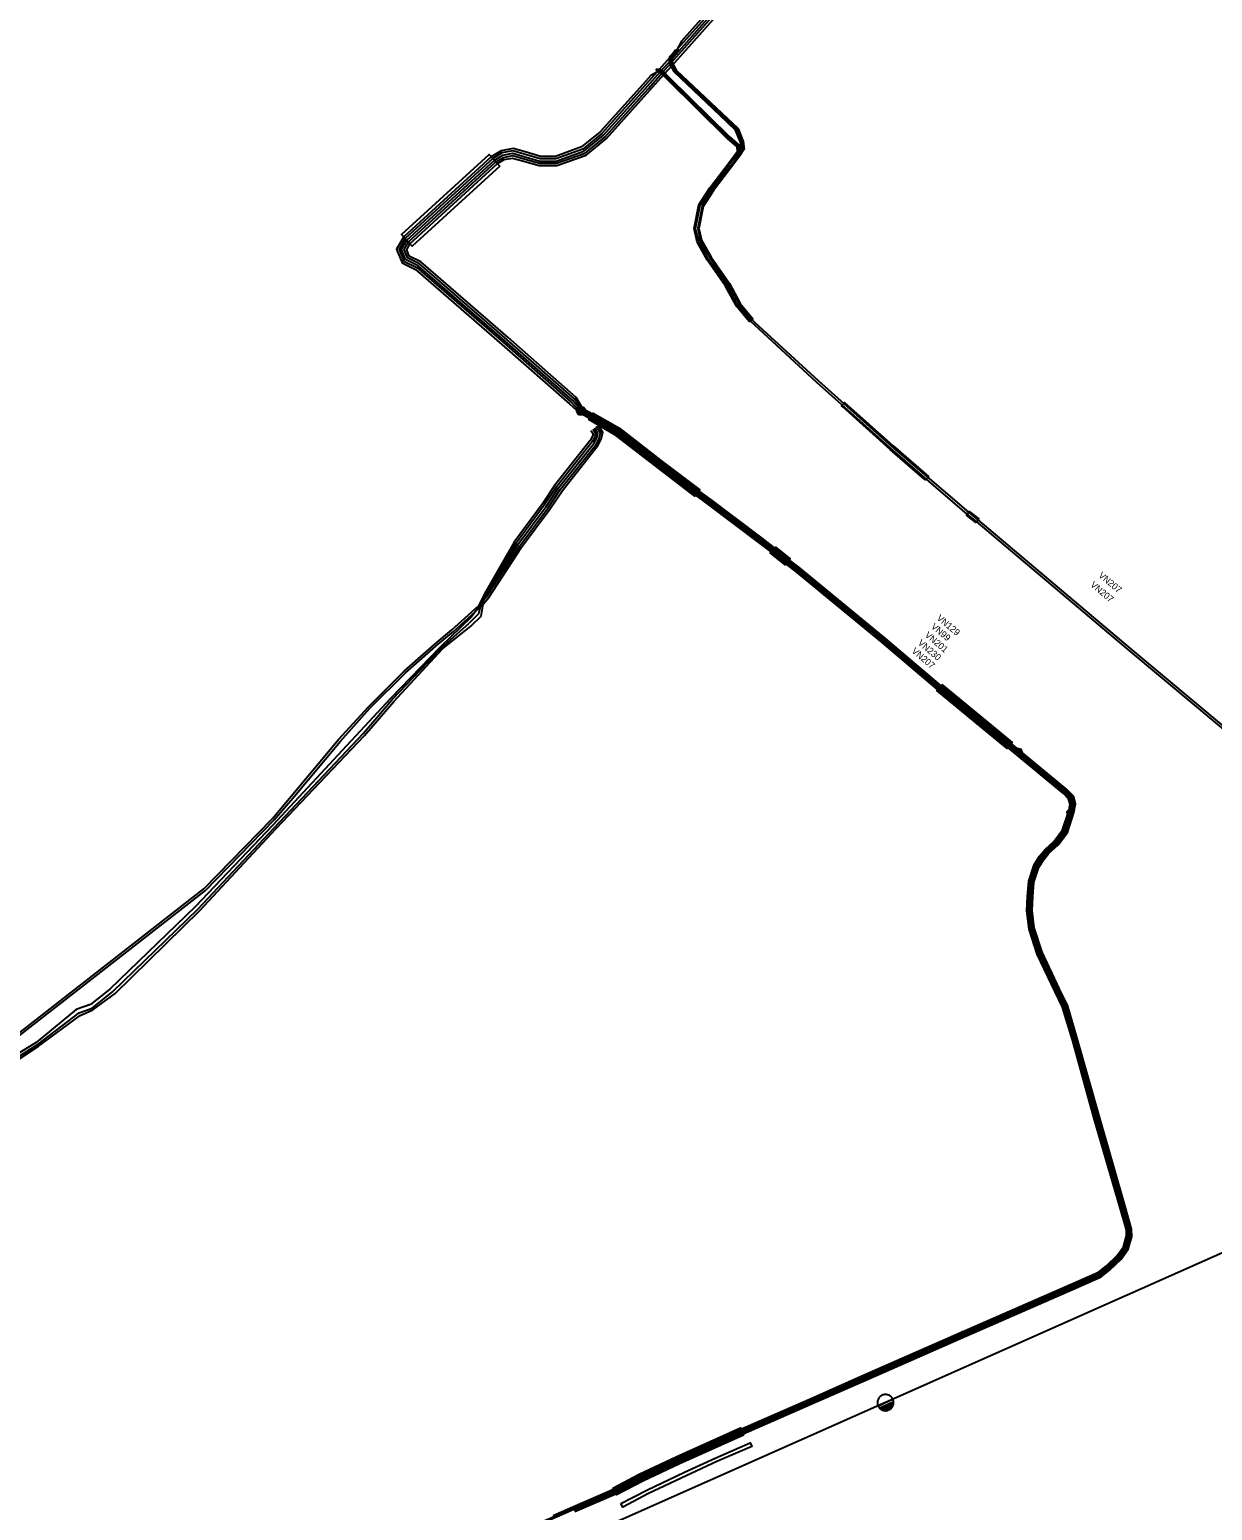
# Model space of a CAD drawing. Extents: x -643811 to -636362, y -1117362 to -1108614.
# Drawn here: x -640773 to -640592.9, y -1115901 to -1115675.5 of the extents above; entities that cross this region are included whole.
import ezdxf

# ---------------------------------------------------------------- set-up
doc = ezdxf.new("R2010")
doc.units = 0
for name, color, linetype in [('1', 7, 'Continuous'), ('13', 7, 'Continuous'), ('19', 7, 'Continuous'), ('20', 7, 'Continuous'), ('5', 7, 'Continuous'), ('7', 7, 'Continuous'), ('9', 7, 'Continuous')]:
    doc.layers.add(name, color=color, linetype=linetype)

# ---------------------------------------------------------------- blocks, each defined once
blk = doc.blocks.new('VN440')
at = {"layer": '13'}
for points in [[(1.22, 0), (1.21, 0.13), (1.19, 0.25), (1.16, 0.38), (1.11, 0.5), (1.05, 0.61), (0.98, 0.72), (0.9, 0.82), (0.81, 0.91), (0.71, 0.99), (0.6, 1.06), (0.49, 1.12), (0.37, 1.16), (0.25, 1.2), (0.12, 1.22), (-0.01, 1.22), (-0.14, 1.22), (-0.26, 1.2), (-0.39, 1.16), (-0.51, 1.12), (-0.62, 1.06), (-0.73, 0.99), (-0.83, 0.91), (-0.92, 0.82), (-1, 0.72), (-1.07, 0.61), (-1.13, 0.5), (-1.18, 0.38), (-1.21, 0.25), (-1.23, 0.13), (-1.24, 0), (-1.23, -0.13), (-1.21, -0.26), (-1.18, -0.38), (-1.13, -0.5), (-1.07, -0.62), (-1, -0.73), (-0.92, -0.83), (-0.83, -0.92), (-0.73, -1), (-0.62, -1.07), (-0.51, -1.13), (-0.39, -1.17), (-0.26, -1.2), (-0.14, -1.23), (-0.01, -1.23), (0.12, -1.23), (0.25, -1.2), (0.37, -1.17), (0.49, -1.13), (0.6, -1.07), (0.71, -1), (0.81, -0.92), (0.9, -0.83), (0.98, -0.73), (1.05, -0.62), (1.11, -0.5), (1.16, -0.38), (1.19, -0.26), (1.21, -0.13), (1.22, 0)], [(-1.24, 0), (1.22, 0)], [(-1.18, -0.34), (1.1, -0.34)], [(-1.01, -0.63), (0.97, -0.63)], [(-0.74, -0.92), (0.68, -0.92)]]:
    blk.add_lwpolyline(points, dxfattribs=at)
blk = doc.blocks.new('VN870')
at = {"layer": '19'}
for points in [[(0, -0.25), (0.5, 0), (0, 0.25), (-0.5, 0), (0, -0.25)], [(0.37, 0), (0, 0.19), (-0.36, 0), (0, -0.19), (0.37, 0)], [(0.24, 0), (0, 0.12), (-0.25, 0), (0, -0.12), (0.24, 0)], [(0.12, 0), (0, 0.06), (-0.13, 0), (0, -0.06), (0.12, 0)]]:
    blk.add_lwpolyline(points, dxfattribs=at)

msp = doc.modelspace()

# ---------------------------------------------------------------- linework, layer by layer
at = {"layer": '1'}
msp.add_lwpolyline([(-640174.13, -1115803.89), (-640251.81, -1115797.69), (-640320.19, -1115797.01), (-640382.28, -1115796.07), (-640441.87, -1115795.49), (-640509.03, -1115825.24), (-640529.18, -1115834.18), (-640529.51, -1115834.33), (-640569.54, -1115852.09), (-640642.67, -1115884.59), (-640695.7, -1115908.15), (-640695.88, -1115908.23), (-640712.05, -1115915.41), (-640778.4, -1115945.12), (-640781.72, -1115942.1), (-640781.89, -1115941.95), (-640782.05, -1115941.8), (-640782.21, -1115941.65), (-640782.37, -1115941.51), (-640806.72, -1115919.38), (-640845, -1115909.84)], dxfattribs=at)
at = {"layer": '20'}
for points in [[(-640674.7, -1115681.77), (-640674.87, -1115681.87), (-640675.56, -1115680.63), (-640675.5, -1115679.58), (-640674.75, -1115678.76), (-640674.45, -1115679.03), (-640675.1, -1115679.74), (-640675.16, -1115680.53), (-640674.54, -1115681.65), (-640674.53, -1115681.67)], [(-640675.72, -1115682.97), (-640675.86, -1115683.11), (-640676.77, -1115682.16), (-640677.21, -1115681.95), (-640677.03, -1115681.59), (-640676.53, -1115681.84), (-640675.58, -1115682.83), (-640675.58, -1115682.83)], [(-640675.58, -1115682.83), (-640675.58, -1115682.83), (-640666.48, -1115691.79), (-640666.48, -1115691.79), (-640666.62, -1115691.93), (-640666.76, -1115692.07), (-640675.86, -1115683.11), (-640675.72, -1115682.97)], [(-640674.7, -1115681.77), (-640674.56, -1115681.62), (-640674.54, -1115681.65), (-640667.55, -1115688.28), (-640665.18, -1115690.53), (-640665.32, -1115690.68), (-640665.46, -1115690.82), (-640665.49, -1115690.8), (-640667.83, -1115688.57), (-640674.84, -1115681.91)], [(-640666.62, -1115691.93), (-640666.49, -1115691.78), (-640666.48, -1115691.79), (-640664.87, -1115693.18), (-640664.83, -1115693.91), (-640664.82, -1115694.04), (-640664.92, -1115694.04), (-640665.02, -1115694.05), (-640665.22, -1115694.06), (-640665.22, -1115693.99), (-640665.26, -1115693.37), (-640666.75, -1115692.08)], [(-640665.32, -1115690.68), (-640665.13, -1115690.61), (-640664.35, -1115692.52), (-640664.19, -1115693.68), (-640664.61, -1115694.3), (-640664.94, -1115694.07), (-640664.92, -1115694.04), (-640664.83, -1115693.91), (-640664.61, -1115693.58), (-640664.75, -1115692.62), (-640665.49, -1115690.8), (-640665.51, -1115690.76)], [(-640665.22, -1115693.99), (-640665.18, -1115693.93), (-640665.02, -1115694.05), (-640664.62, -1115694.34), (-640665.78, -1115695.95), (-640668.87, -1115700.01), (-640670.43, -1115702.44), (-640671.08, -1115705.78), (-640670.68, -1115707.56), (-640669.23, -1115710.17), (-640666.42, -1115714.18), (-640664.78, -1115717.23), (-640662.88, -1115719.52), (-640663.42, -1115719.97), (-640665.37, -1115717.62), (-640667.02, -1115714.55), (-640669.82, -1115710.55), (-640671.34, -1115707.81), (-640671.79, -1115705.79), (-640671.09, -1115702.17), (-640669.44, -1115699.6), (-640666.34, -1115695.53)], [(-640701.4, -1115696.27), (-640714.73, -1115708.47), (-640716.35, -1115706.7), (-640703.02, -1115694.5)], [(-640649.19, -1115732.97), (-640649.37, -1115732.81), (-640648.9, -1115732.29), (-640641.51, -1115738.89), (-640636.15, -1115743.53), (-640636.61, -1115744.06), (-640636.97, -1115743.75), (-640641.97, -1115739.42)], [(-640687.26, -1115733.85), (-640683.19, -1115736.21), (-640683.12, -1115736.25), (-640676.46, -1115741.4), (-640670.96, -1115745.58), (-640671.68, -1115746.54), (-640677.2, -1115742.36), (-640683.8, -1115737.25), (-640687.86, -1115734.89)], [(-640630.13, -1115749.16), (-640629.93, -1115748.91), (-640628.49, -1115750.02), (-640628.74, -1115750.34), (-640628.92, -1115750.58), (-640630.36, -1115749.46)], [(-640659.46, -1115754.26), (-640657.2, -1115756.08), (-640657.96, -1115757.02), (-640660.22, -1115755.2)], [(-640634.12, -1115775.23), (-640623.39, -1115784.07), (-640624.15, -1115784.99), (-640634.88, -1115776.15)], [(-640684.2, -1115897.6), (-640680.19, -1115895.51), (-640674.53, -1115892.84), (-640664.77, -1115888.44), (-640664.29, -1115889.54), (-640674.03, -1115893.94), (-640679.63, -1115896.58), (-640683.64, -1115898.66)], [(-640682.96, -1115899.97), (-640679.03, -1115897.93), (-640673.28, -1115895.19), (-640668.61, -1115893.03), (-640663.29, -1115890.72), (-640663.05, -1115891.27), (-640668.37, -1115893.57), (-640673.02, -1115895.73), (-640678.76, -1115898.46), (-640682.68, -1115900.51)]]:
    msp.add_lwpolyline(points, close=True, dxfattribs=at)
at = {"layer": '5'}
for points in [[(-640595.84, -1115583.46), (-640600.55, -1115588.86), (-640608.04, -1115597.9), (-640613.88, -1115605.07), (-640619.92, -1115612.2), (-640634.62, -1115629.42), (-640648.36, -1115645.76), (-640650.75, -1115648.6), (-640669.54, -1115672.54), (-640673.71, -1115677.27), (-640674.38, -1115678.49), (-640674.6, -1115678.9)], [(-640669.28, -1115672.77), (-640674.38, -1115678.49), (-640677.48, -1115681.97), (-640679.21, -1115683.92), (-640685.86, -1115691.33), (-640688.77, -1115693.68), (-640692.89, -1115695.16), (-640695.26, -1115695.16), (-640697.67, -1115694.46), (-640699.4, -1115693.97), (-640701.09, -1115694.28), (-640702.45, -1115695.13), (-640715.78, -1115707.33), (-640716.73, -1115708.95), (-640716.01, -1115710.75), (-640714.02, -1115711.75), (-640700.85, -1115723.16), (-640690.51, -1115732.24), (-640689.14, -1115733.72)], [(-640689.01, -1115733.56), (-640690.26, -1115731.99), (-640700.65, -1115722.88), (-640713.82, -1115711.46), (-640715.73, -1115710.5), (-640716.34, -1115708.97), (-640715.54, -1115707.58), (-640702.21, -1115695.38), (-640700.96, -1115694.61), (-640699.41, -1115694.33), (-640697.76, -1115694.8), (-640695.31, -1115695.51), (-640692.82, -1115695.51), (-640688.6, -1115693.99), (-640685.63, -1115691.59), (-640678.93, -1115684.13), (-640676.92, -1115681.87), (-640675.33, -1115680.08), (-640669.01, -1115673)], [(-640688.88, -1115733.4), (-640690, -1115731.75), (-640700.35, -1115722.67), (-640713.63, -1115711.16), (-640715.45, -1115710.24), (-640715.96, -1115709), (-640715.31, -1115707.84), (-640701.98, -1115695.64), (-640700.83, -1115694.95), (-640699.43, -1115694.69), (-640697.87, -1115695.13), (-640695.36, -1115695.86), (-640692.76, -1115695.86), (-640688.42, -1115694.3), (-640685.38, -1115691.84), (-640678.82, -1115684.52), (-640676.61, -1115682.04), (-640675.34, -1115680.62), (-640668.74, -1115673.22)], [(-640688.75, -1115733.25), (-640689.75, -1115731.51), (-640700.13, -1115722.4), (-640713.43, -1115710.87), (-640715.18, -1115709.99), (-640715.57, -1115709.02), (-640715.07, -1115708.1), (-640701.74, -1115695.9), (-640700.71, -1115695.28), (-640699.45, -1115695.05), (-640697.95, -1115695.47), (-640695.41, -1115696.21), (-640692.7, -1115696.21), (-640688.25, -1115694.61), (-640685.14, -1115692.1), (-640678.54, -1115684.74), (-640676.36, -1115682.3), (-640675.16, -1115680.94), (-640668.47, -1115673.44)], [(-640674.6, -1115678.9), (-640675.3, -1115679.66), (-640675.33, -1115680.08), (-640675.36, -1115680.58), (-640675.34, -1115680.62), (-640675.16, -1115680.94), (-640674.7, -1115681.77), (-640667.69, -1115688.42), (-640665.32, -1115690.68), (-640664.55, -1115692.57), (-640664.4, -1115693.63), (-640665.76, -1115695.66), (-640669.05, -1115699.89), (-640670.61, -1115702.41), (-640671.23, -1115705.79), (-640670.87, -1115707.74), (-640669.44, -1115710.22), (-640666.61, -1115714.25), (-640665.03, -1115717.27), (-640663.16, -1115719.52), (-640652.94, -1115728.93), (-640641.61, -1115739.09), (-640630.06, -1115749.01), (-640628.62, -1115750.14), (-640605.49, -1115769.68), (-640586.08, -1115785.91)], [(-640677.12, -1115681.77), (-640677.48, -1115681.97), (-640678.41, -1115682.49), (-640679.63, -1115683.86), (-640686.11, -1115691.08), (-640688.95, -1115693.37), (-640692.94, -1115694.81), (-640695.21, -1115694.81), (-640697.56, -1115694.12), (-640699.38, -1115693.61), (-640701.21, -1115693.95), (-640702.69, -1115694.87), (-640716.02, -1115707.07), (-640717.11, -1115708.93), (-640716.28, -1115711), (-640714.22, -1115712.04), (-640701.07, -1115723.44), (-640690.77, -1115732.48), (-640689.27, -1115733.87)], [(-640586.28, -1115786.16), (-640605.66, -1115769.93), (-640628.8, -1115750.42), (-640630.24, -1115749.3), (-640641.84, -1115739.27), (-640653.13, -1115729.23), (-640663.27, -1115719.84), (-640665.2, -1115717.51), (-640666.85, -1115714.44), (-640669.65, -1115710.44), (-640671.15, -1115707.74), (-640671.59, -1115705.79), (-640670.9, -1115702.25), (-640669.28, -1115699.72), (-640666.18, -1115695.65), (-640665.02, -1115694.05), (-640665.06, -1115693.28), (-640666.62, -1115691.93), (-640675.72, -1115682.97), (-640676.36, -1115682.3), (-640676.61, -1115682.04), (-640676.65, -1115682), (-640676.92, -1115681.87), (-640677.12, -1115681.77)], [(-640696.98, -1115903.63), (-640690.21, -1115900.65), (-640684.01, -1115897.95), (-640679.99, -1115895.86), (-640674.36, -1115893.21), (-640664.61, -1115888.81), (-640653.45, -1115883.94), (-640645.83, -1115880.57), (-640631.38, -1115874.22), (-640614.45, -1115866.82), (-640610.16, -1115864.9), (-640608.9, -1115863.93), (-640607.23, -1115862.34), (-640606.26, -1115860.97), (-640605.76, -1115859.21), (-640605.8, -1115858.27), (-640606.78, -1115854.9), (-640610.75, -1115841.1), (-640614.04, -1115829.31), (-640615.54, -1115824.27), (-640616.72, -1115821.87), (-640619.39, -1115816.24), (-640620.62, -1115812.43), (-640620.95, -1115809.7), (-640620.86, -1115807.51), (-640620.68, -1115805.22), (-640619.88, -1115802.78), (-640619.05, -1115801.51), (-640618.25, -1115800.52), (-640616.85, -1115799.23), (-640615.53, -1115797.49), (-640614.57, -1115794.57), (-640614.36, -1115793.44), (-640614.61, -1115792.53), (-640615.47, -1115791.66), (-640623.37, -1115785.12), (-640634.63, -1115775.84), (-640643.07, -1115768.68), (-640656.24, -1115757.83), (-640657.7, -1115756.71), (-640659.96, -1115754.89), (-640661.83, -1115753.45), (-640669.65, -1115747.55), (-640671.44, -1115746.22), (-640676.95, -1115742.04), (-640683.57, -1115736.92), (-640685.27, -1115735.94), (-640687.66, -1115734.54), (-640689.14, -1115733.72)], [(-640696.93, -1115903.82), (-640690.13, -1115900.83), (-640683.92, -1115898.13), (-640679.9, -1115896.04), (-640674.28, -1115893.39), (-640664.53, -1115888.99), (-640653.37, -1115884.12), (-640645.75, -1115880.75), (-640631.3, -1115874.4), (-640614.37, -1115867), (-640610.06, -1115865.07), (-640608.77, -1115864.08), (-640607.08, -1115862.47), (-640606.08, -1115861.06), (-640605.56, -1115859.23), (-640605.6, -1115858.24), (-640606.59, -1115854.84), (-640610.56, -1115841.04), (-640613.85, -1115829.26), (-640615.35, -1115824.2), (-640616.54, -1115821.78), (-640619.2, -1115816.17), (-640620.42, -1115812.39), (-640620.75, -1115809.69), (-640620.66, -1115807.52), (-640620.48, -1115805.26), (-640619.7, -1115802.87), (-640618.89, -1115801.63), (-640618.1, -1115800.66), (-640616.7, -1115799.37), (-640615.35, -1115797.58), (-640614.38, -1115794.62), (-640614.16, -1115793.43), (-640614.43, -1115792.43), (-640615.33, -1115791.51), (-640623.24, -1115784.97), (-640634.5, -1115775.69), (-640642.94, -1115768.53), (-640656.12, -1115757.67), (-640657.58, -1115756.55), (-640659.84, -1115754.73), (-640661.71, -1115753.29), (-640669.53, -1115747.39), (-640671.32, -1115746.06), (-640676.83, -1115741.88), (-640683.46, -1115736.75), (-640685.17, -1115735.77), (-640687.56, -1115734.37), (-640689.01, -1115733.56)], [(-640693.28, -1115901.78), (-640690.29, -1115900.46), (-640684.09, -1115897.77), (-640680.08, -1115895.68), (-640674.45, -1115893.03), (-640664.69, -1115888.62), (-640653.53, -1115883.75), (-640645.91, -1115880.38), (-640631.46, -1115874.03), (-640614.53, -1115866.63), (-640610.27, -1115864.72), (-640609.03, -1115863.78), (-640607.38, -1115862.21), (-640606.45, -1115860.89), (-640605.96, -1115859.18), (-640606, -1115858.3), (-640606.97, -1115854.95), (-640610.95, -1115841.15), (-640614.23, -1115829.37), (-640615.72, -1115824.35), (-640616.9, -1115821.95), (-640619.57, -1115816.32), (-640620.81, -1115812.48), (-640621.15, -1115809.71), (-640621.06, -1115807.5), (-640620.87, -1115805.18), (-640620.06, -1115802.7), (-640619.21, -1115801.39), (-640618.39, -1115800.38), (-640617, -1115799.1), (-640615.71, -1115797.39), (-640614.77, -1115794.52), (-640614.57, -1115793.45), (-640614.79, -1115792.63), (-640615.6, -1115791.81), (-640623.5, -1115785.28), (-640634.76, -1115776), (-640643.2, -1115768.84), (-640656.37, -1115757.98), (-640657.83, -1115756.86), (-640660.09, -1115755.04), (-640661.95, -1115753.61), (-640669.77, -1115747.71), (-640671.56, -1115746.38), (-640677.07, -1115742.2), (-640683.68, -1115737.08), (-640685.37, -1115736.12), (-640687.76, -1115734.72), (-640689.27, -1115733.87)], [(-640690.05, -1115901.01), (-640683.83, -1115898.31), (-640679.81, -1115896.22), (-640674.2, -1115893.57), (-640664.45, -1115889.17), (-640653.29, -1115884.3), (-640645.67, -1115880.93), (-640631.22, -1115874.58), (-640614.29, -1115867.18), (-640609.96, -1115865.24), (-640608.64, -1115864.23), (-640606.93, -1115862.6), (-640605.9, -1115861.15), (-640605.36, -1115859.25), (-640605.4, -1115858.21), (-640606.4, -1115854.78), (-640610.37, -1115840.98), (-640613.66, -1115829.2), (-640615.16, -1115824.13), (-640616.36, -1115821.69), (-640619.01, -1115816.1), (-640620.22, -1115812.35), (-640620.55, -1115809.68), (-640620.46, -1115807.53), (-640620.28, -1115805.3), (-640619.52, -1115802.96), (-640618.73, -1115801.75), (-640617.95, -1115800.8), (-640616.55, -1115799.51), (-640615.17, -1115797.67), (-640614.19, -1115794.67), (-640613.96, -1115793.42), (-640614.25, -1115792.33), (-640615.19, -1115791.36), (-640623.11, -1115784.82), (-640634.37, -1115775.54), (-640642.81, -1115768.38), (-640656, -1115757.51), (-640657.46, -1115756.39), (-640659.72, -1115754.57), (-640661.59, -1115753.13), (-640669.41, -1115747.23), (-640671.2, -1115745.9), (-640676.71, -1115741.72), (-640683.35, -1115736.58), (-640685.07, -1115735.6), (-640687.46, -1115734.2), (-640688.88, -1115733.4)], [(-640689.97, -1115901.2), (-640683.75, -1115898.49), (-640679.72, -1115896.4), (-640674.11, -1115893.75), (-640664.37, -1115889.36), (-640653.21, -1115884.49), (-640645.59, -1115881.12), (-640631.14, -1115874.77), (-640614.21, -1115867.37), (-640609.85, -1115865.42), (-640608.51, -1115864.38), (-640606.78, -1115862.73), (-640605.71, -1115861.23), (-640605.16, -1115859.28), (-640605.2, -1115858.18), (-640606.21, -1115854.73), (-640610.17, -1115840.93), (-640613.47, -1115829.15), (-640614.98, -1115824.05), (-640616.18, -1115821.61), (-640618.83, -1115816.02), (-640620.03, -1115812.3), (-640620.35, -1115809.67), (-640620.26, -1115807.54), (-640620.09, -1115805.34), (-640619.34, -1115803.04), (-640618.57, -1115801.87), (-640617.81, -1115800.93), (-640616.4, -1115799.64), (-640614.99, -1115797.77), (-640613.99, -1115794.72), (-640613.75, -1115793.41), (-640614.07, -1115792.22), (-640615.06, -1115791.21), (-640622.99, -1115784.66), (-640634.24, -1115775.38), (-640642.68, -1115768.22), (-640655.87, -1115757.36), (-640657.33, -1115756.24), (-640659.59, -1115754.42), (-640661.47, -1115752.97), (-640669.29, -1115747.07), (-640671.08, -1115745.74), (-640676.59, -1115741.56), (-640683.24, -1115736.42), (-640684.97, -1115735.42), (-640687.36, -1115734.02), (-640688.75, -1115733.25)]]:
    msp.add_lwpolyline(points, dxfattribs=at)
at = {"layer": '9'}
for points in [[(-640775.65, -1115829.12), (-640746.45, -1115806.34), (-640736, -1115795.62), (-640733.14, -1115792.23), (-640725.94, -1115783.61), (-640721.41, -1115778.61), (-640715.97, -1115773.18), (-640711.31, -1115769.08), (-640708.71, -1115766.89), (-640704.66, -1115763.24), (-640704.33, -1115762.95), (-640704.23, -1115762.82), (-640703.83, -1115762.33), (-640703.42, -1115761.84), (-640698.35, -1115754.13), (-640694.04, -1115748.31), (-640692.15, -1115745.49), (-640686.75, -1115738.66), (-640686.27, -1115737.77), (-640686.09, -1115736.9), (-640686.65, -1115735.95)], [(-640775.45, -1115829.41), (-640746.22, -1115806.6), (-640735.74, -1115795.85), (-640732.92, -1115792.52), (-640725.67, -1115783.84), (-640721.16, -1115778.86), (-640715.73, -1115773.44), (-640711.08, -1115769.34), (-640708.47, -1115767.14), (-640705.17, -1115764.17), (-640704.39, -1115763.47), (-640704.08, -1115763.19), (-640703.93, -1115763.01), (-640703.14, -1115762.05), (-640698.07, -1115754.33), (-640693.76, -1115748.52), (-640691.87, -1115745.7), (-640686.46, -1115738.85), (-640685.94, -1115737.89), (-640685.72, -1115736.84), (-640686.36, -1115735.75)], [(-640687.23, -1115736.35), (-640686.83, -1115737.02), (-640686.93, -1115737.52), (-640687.34, -1115738.27), (-640692.72, -1115745.08), (-640694.62, -1115747.91), (-640698.93, -1115753.72), (-640704.08, -1115762.23), (-640704.23, -1115762.82), (-640704.39, -1115763.47), (-640704.64, -1115764.48), (-640706.07, -1115765.89)], [(-640705.82, -1115766.36), (-640704.22, -1115764.83), (-640703.93, -1115763.01), (-640703.83, -1115762.33), (-640703.79, -1115762.1), (-640698.64, -1115753.93), (-640694.32, -1115748.1), (-640692.44, -1115745.29), (-640687.05, -1115738.46), (-640686.6, -1115737.65), (-640686.46, -1115736.96), (-640686.94, -1115736.15)], [(-640687.52, -1115736.55), (-640687.2, -1115737.08), (-640687.27, -1115737.4), (-640687.64, -1115738.08), (-640693, -1115744.87), (-640694.9, -1115747.7), (-640699.22, -1115753.53), (-640703.75, -1115761.43), (-640704.66, -1115763.24), (-640705.03, -1115763.98), (-640705.17, -1115764.17), (-640705.72, -1115764.93)], [(-640922.22, -1115919.55), (-640914.54, -1115915.43), (-640909.61, -1115912.62), (-640902.02, -1115907.69), (-640894.52, -1115902.1), (-640888.73, -1115897.2), (-640825.74, -1115861.36), (-640823.6, -1115860.13), (-640823.29, -1115859.95), (-640818.38, -1115857.12), (-640808.01, -1115851.2), (-640801.43, -1115846.35), (-640790.97, -1115841.54), (-640778.58, -1115834.38), (-640771.68, -1115830.02), (-640765.43, -1115825.23), (-640763.48, -1115824.5), (-640760.33, -1115822), (-640747.35, -1115809.45), (-640735.75, -1115797.04), (-640722.21, -1115782.69), (-640717.76, -1115777.52), (-640710.27, -1115769.66), (-640706.07, -1115765.89)], [(-640778.27, -1115834.7), (-640771.61, -1115830.33), (-640765.3, -1115825.62), (-640763.36, -1115824.76), (-640759.98, -1115822.31), (-640747.07, -1115809.67), (-640735.52, -1115797.22), (-640722, -1115782.98), (-640717.55, -1115777.8), (-640710.12, -1115769.79), (-640705.82, -1115766.36)], [(-640705.72, -1115764.93), (-640710.49, -1115769.54), (-640718.03, -1115777.36), (-640736, -1115796.71)], [(-640736, -1115796.71), (-640747.8, -1115809.07), (-640760.79, -1115821.64), (-640763.73, -1115823.98), (-640765.87, -1115824.75), (-640771.99, -1115829.76), (-640778.63, -1115833.83), (-640791.21, -1115841.2), (-640801.66, -1115845.76), (-640808.3, -1115850.8), (-640818.52, -1115856.74), (-640823.52, -1115859.53), (-640823.82, -1115859.7), (-640825.97, -1115860.91), (-640889.18, -1115896.76), (-640894.76, -1115901.83), (-640902.2, -1115907.6), (-640909.81, -1115912.38), (-640914.84, -1115915.34), (-640922.83, -1115919.43)]]:
    msp.add_lwpolyline(points, dxfattribs=at)

# ---------------------------------------------------------------- block references
at = {"layer": '13', "rotation": 24}
msp.add_blockref('VN440', (-640642.67, -1115884.59), dxfattribs=at)
at = {"layer": '19'}
for p, rotation in [((-640674.6, -1115678.9), 48), ((-640677.12, -1115681.77), -26.000000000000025), ((-640689.27, -1115733.87), -28.99999999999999), ((-640689.14, -1115733.72), -28.99999999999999), ((-640689.01, -1115733.56), -28.99999999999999), ((-640688.88, -1115733.41), -28.99999999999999), ((-640688.75, -1115733.25), -28.99999999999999), ((-640658.75, -1115755.1), -37.99999999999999), ((-640658.31, -1115755.71), -37.99999999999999), ((-640622.2, -1115785.31), -39.00000000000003), ((-640614.83, -1115794.7), 72), ((-640630.96, -1115874.03), -156.00000000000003)]:
    msp.add_blockref('VN870', p, dxfattribs=dict(at, rotation=rotation))

# ---------------------------------------------------------------- texts
at = {"layer": '7'}
for s, rotation, p in [('VN207', 319.8648, (-640611.57, -1115760.19)), ('VN207', 319.8092, (-640610.33, -1115758.76)), ('VN99', 319.6907, (-640635.82, -1115766.55)), ('VN129', 319.6907, (-640634.96, -1115765.26)), ('VN230', 319.6907, (-640637.83, -1115769.04)), ('VN201', 319.6907, (-640636.77, -1115767.84)), ('VN207', 319.6934, (-640638.78, -1115770.28))]:
    msp.add_text(s, height=0.994, rotation=rotation, dxfattribs=at).set_placement(p)

doc.saveas('drawing.dxf')
